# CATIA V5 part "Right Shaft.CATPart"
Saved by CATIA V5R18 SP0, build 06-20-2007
Part number: Right hand shaft
Bounding box of the stored display mesh (mm): x 0 to 100, y -35 to 35, z -35 to 35
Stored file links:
  D:\Shriniwas\v5_r19\c16_CAT_v5r19\c16_Part\CV Joint\Right hand shaft.CATPart
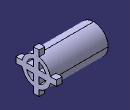
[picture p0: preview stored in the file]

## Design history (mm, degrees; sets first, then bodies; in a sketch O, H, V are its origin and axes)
Body1 (main body)
  Sketch1 on yz-plane, origin (0, 0, 0), H (0, 1, 0), V (0, 0, 1)
    circle A1 centre (0, 0) radius 25
    circle A2 centre (0, 0) radius 17.5
    radius A1 = 25
    radius A2 = 17.5
  Pad1: profile Sketch1, direction (1, 0, 0), length 100
  Sketch2 on end face of Pad1, origin (100, 0, 0), H (0, 1, 0), V (0, 0, 1)
    line L1 (5, 35) -> (5, -35)
    line L2 (5, -35) -> (-5, -35)
    line L3 (-5, -35) -> (-5, 35)
    line L4 (-5, 35) -> (5, 35)
    length L1 = 70
    length L4 = 10
    vertical: L1 V, L3 V
    horizontal: L2 H, L4 H
    equidistance: L1 L3 O, L2 L4 O
  Pad2: profile Sketch2, direction (-1, 0, 0), length 10
  CircPattern1: of the body so far, instances 2, angular step 90, axis from face of Pad1 from Sketch1.A1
